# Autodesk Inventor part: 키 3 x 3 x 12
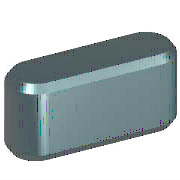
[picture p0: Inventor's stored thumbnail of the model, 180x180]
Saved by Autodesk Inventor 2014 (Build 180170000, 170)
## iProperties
Created: 2012-02
Part Number: 키 3 x 3 x 12
Material: 강철, 연강
Description: 키 및 해당 키홈
Document SubType Name: Modeling
Standard: KS B 1311
Designer: mduedu
Standards Organization: KS
Language: ko-KR
Size Designation: 3 x 3 x 12
Categories: <MemberInstance><Categories><Category DisplayName="샤프트 부품" InternalName="7f7aeb1f-a693-4053-b835-cee3144e0d98" Mnemonic="SHFT"><Category DisplayName="키" Interna
Density: 7.86 g/cm^3
Appearance: 강철
Mass: 0.790122 g
Surface Area: 1.42216 cm^2
Volume: 0.100524 cm^3
IsCustomPart: 1
Author: mduedu
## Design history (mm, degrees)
workplane "Work Plane1"
workplane "Work Plane2"
sketch "스케치1"
  geometry: L1 (1.5, 1.5)-(10.5, 1.5); L2 (10.5, -1.5)-(1.5, -1.5); L3 (0, 9.4)-(0, -7.4) reference; L4 (-5, 0)-(30, 0) reference; L5 (12, 0)-(12, 7); A1 r 1.5 centre (1.5, 0) between (1.5, 1.5) and (1.5, -1.5); A2 r 1.5 centre (10.5, 0) between (10.5, -1.5) and (10.5, 1.5)
  constraints: 6 end point, 5 point on circle, 4 tangent, 3 point on line, 2 centre point, 1 horizontal, 1 parallel, 1 perpendicular
  dimensions: "d0" = 1.5 radius of A1 (= 0.5 x PB); "d13" = 1.5 radius of A2 (= 0.5 x PB); "d14" = 12 distance between parallel lines of L5 L3 (= NLG)
extrude "본체1" new body sketch "스케치1" taper "d3" = 0 deg; stored distance "d4" = 10
workplane "Work Plane3"
body "Solid1"
chamfer "모따기1" distance "d8" = 0.25 (= PHH); stored, may be unused: second distance "d9" = 0.25 (= PHH), angle "d15" = 45 deg
other parameters: "d1" = -1.8 (= -PNT), "d2" = 1.2 (= PH - PNT), "NLG" = 12 [user parameter; used in 3 equation terms], "PB" = 3 [user parameter; used in 2 equation terms], "PNT" = 1.8 [user parameter; used in 2 equation terms], "PH" = 3 [user parameter; used in 1 equation term], "PHH" = 0.25 [user parameter; used in 2 equation terms], "d10" = 0, "d16" = 0, "d17" = 0, "d18" = 0, "WDMIN" = 8 [user parameter], "PLB2" = 12 (= NLG) [user parameter], "PLB1" = 12 (= NLG) [user parameter], "RR" = 0.08 [user parameter], "PUEB" = 1.4 [user parameter]
